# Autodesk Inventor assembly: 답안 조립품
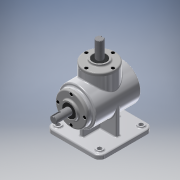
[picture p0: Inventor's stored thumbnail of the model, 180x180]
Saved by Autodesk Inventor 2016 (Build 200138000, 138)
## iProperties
Created: 2015-07
Part Number: 답안 조립품
Document SubType Name: Assembly
Designer: Administrator
Author: Administrator
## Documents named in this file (14)
- C:\Users\Administrator\Desktop\450706V1007\답안 조립품.iam
- C:\Users\Administrator\Desktop\450706V1007\본체.ipt
- C:\Users\Administrator\Desktop\450706V1007\커버.ipt
- C:\Users\Administrator\Desktop\450706V1007\메인 축.ipt
- 메인 축.ipt
- C:\Users\Administrator\Desktop\450706V1007\키 5x5.ipt
- C:\Users\Administrator\Desktop\450706V1007\메인 베벨기어.ipt
- C:\Users\Administrator\Desktop\450706V1007\베어링 6203.ipt
- C:\Users\Administrator\Desktop\450706V1007\서브 축.ipt
- 서브 축.ipt
- C:\Users\Administrator\Desktop\450706V1007\키 4x4.ipt
- C:\Users\Administrator\Desktop\450706V1007\서브 베벨기어.ipt
- C:\Users\Administrator\Desktop\450706V1007\오일실.ipt
- C:\Users\Administrator\Desktop\450706V1007\M4.ipt
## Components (8 placed, 1 different names)
1. M4:1
2. M4:2
3. M4:3
4. M4:4
5. M4:5
6. M4:6
7. M4:7
8. M4:8
